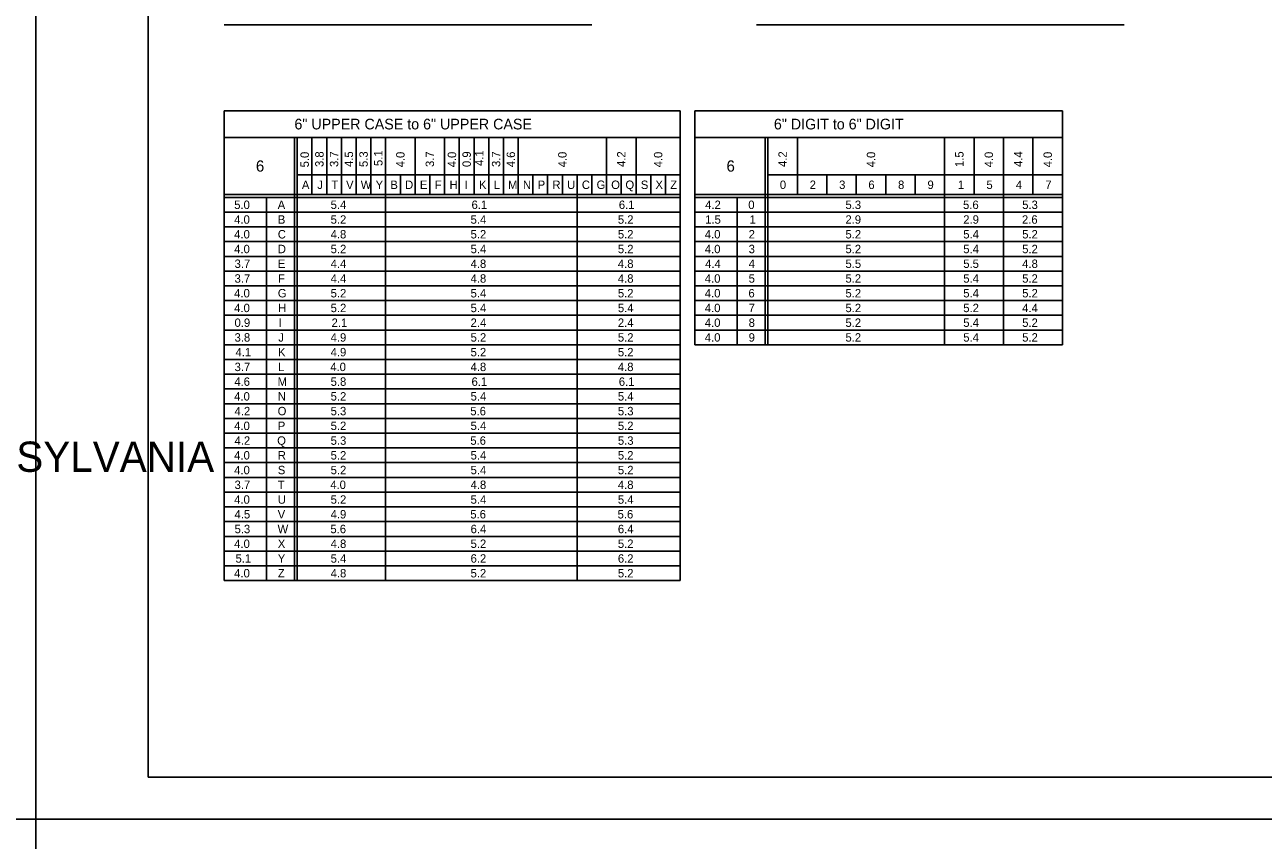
# Model space of a CAD drawing. Extents: x 637580 to 641849, y 297270 to 299646.
# Drawn here: x 640099.4 to 640540.8, y 297856.1 to 298146.6 of the extents above; entities that cross this region are included whole.
import ezdxf

# ---------------------------------------------------------------- set-up
doc = ezdxf.new("R2010")
doc.units = 0
for name, color, linetype in [('1', 7, 'Continuous'), ('2', 7, 'Continuous'), ('XCS-GRID-HVGL', 7, 'Continuous')]:
    doc.layers.add(name, color=color, linetype=linetype)

msp = doc.modelspace()

# ---------------------------------------------------------------- linework, layer by layer
at = {"layer": '1'}
for p, q in [((640143.31, 298442.63), (640143.31, 297878.63)), ((640929.31, 297878.63), (640143.31, 297878.63)), ((640143.31, 297878.63), (640729.31, 297878.63))]:
    msp.add_line(p, q, dxfattribs=at)
at = {"layer": '2'}
for p, q in [((640170.51, 298146.63), (640301.51, 298146.63)), ((640360.21, 298146.63), (640491.21, 298146.63)), ((640333.01, 298116), (640170.51, 298116)), ((640170.51, 298116), (640170.51, 297948.63)), ((640333.01, 298116), (640333.01, 297948.63)), ((640469.26, 298116), (640338.26, 298116)), ((640338.26, 298116), (640338.26, 298032.63)), ((640469.26, 298032.63), (640469.26, 298116)), ((640170.51, 298106.5), (640333.01, 298106.5)), ((640195.51, 298106.5), (640195.51, 297948.63)), ((640196.51, 298106.5), (640196.51, 297948.63)), ((640201.76, 298106.5), (640201.76, 298086.13)), ((640207.01, 298106.5), (640207.01, 298086.13)), ((640212.26, 298106.5), (640212.26, 298086.13)), ((640217.51, 298106.5), (640217.51, 298086.13)), ((640222.76, 298106.5), (640222.76, 298086.13)), ((640228.01, 298106.5), (640228.01, 297948.63)), ((640238.51, 298106.5), (640238.51, 298086.13)), ((640249.01, 298106.5), (640249.01, 298086.13)), ((640254.26, 298106.5), (640254.26, 298086.13)), ((640259.51, 298106.5), (640259.51, 298086.13)), ((640264.76, 298106.5), (640264.76, 298086.13)), ((640270.01, 298106.5), (640270.01, 298086.13)), ((640275.26, 298106.5), (640275.26, 298086.13)), ((640306.76, 298106.5), (640306.76, 298086.13)), ((640317.26, 298106.5), (640317.26, 298086.13)), ((640338.26, 298106.5), (640469.26, 298106.5)), ((640363.26, 298106.5), (640363.26, 298032.63)), ((640364.26, 298106.5), (640364.26, 298032.63)), ((640374.76, 298106.5), (640374.76, 298086.13)), ((640427.26, 298106.5), (640427.26, 298032.63)), ((640437.76, 298106.5), (640437.76, 298086.13)), ((640448.26, 298106.5), (640448.26, 298032.63)), ((640458.76, 298106.5), (640458.76, 298086.13)), ((640196.51, 298093.13), (640333.01, 298093.13)), ((640233.26, 298093.13), (640233.26, 298086.13)), ((640243.76, 298093.13), (640243.76, 298086.13)), ((640280.51, 298093.13), (640280.51, 298086.13)), ((640285.76, 298093.13), (640285.76, 298086.13)), ((640291.01, 298093.13), (640291.01, 298086.13)), ((640291.01, 298093.13), (640291.01, 298086.13)), ((640296.26, 298093.13), (640296.26, 297948.63)), ((640301.51, 298093.13), (640301.51, 298086.13)), ((640312.01, 298093.13), (640312.01, 298086.13)), ((640322.51, 298093.13), (640322.51, 298086.13)), ((640327.76, 298093.13), (640327.76, 298086.13)), ((640364.26, 298093.13), (640469.26, 298093.13)), ((640385.26, 298093.13), (640385.26, 298086.13)), ((640395.76, 298093.13), (640395.76, 298086.13)), ((640406.26, 298093.13), (640406.26, 298086.13)), ((640416.76, 298093.13), (640416.76, 298086.13)), ((640333.01, 298086.13), (640170.51, 298086.13)), ((640469.26, 298086.13), (640338.26, 298086.13)), ((640333.01, 298085.13), (640170.51, 298085.13)), ((640185.51, 298085.13), (640185.51, 297948.63)), ((640469.26, 298085.13), (640338.26, 298085.13)), ((640353.26, 298085.13), (640353.26, 298032.63)), ((640333.01, 298079.88), (640170.51, 298079.88)), ((640469.26, 298079.88), (640338.26, 298079.88)), ((640333.01, 298074.63), (640170.51, 298074.63)), ((640469.26, 298074.63), (640338.26, 298074.63)), ((640333.01, 298069.38), (640170.51, 298069.38)), ((640469.26, 298069.38), (640338.26, 298069.38)), ((640333.01, 298064.13), (640170.51, 298064.13)), ((640469.26, 298064.13), (640338.26, 298064.13)), ((640333.01, 298058.88), (640170.51, 298058.88)), ((640469.26, 298058.88), (640338.26, 298058.88)), ((640333.01, 298053.63), (640170.51, 298053.63)), ((640469.26, 298053.63), (640338.26, 298053.63)), ((640333.01, 298048.38), (640170.51, 298048.38)), ((640469.26, 298048.38), (640338.26, 298048.38)), ((640333.01, 298043.13), (640170.51, 298043.13)), ((640469.26, 298043.13), (640338.26, 298043.13)), ((640333.01, 298037.88), (640170.51, 298037.88)), ((640469.26, 298037.88), (640338.26, 298037.88)), ((640333.01, 298032.63), (640170.51, 298032.63)), ((640338.26, 298032.63), (640469.26, 298032.63)), ((640333.01, 298027.38), (640170.51, 298027.38)), ((640333.01, 298022.13), (640170.51, 298022.13)), ((640333.01, 298016.88), (640170.51, 298016.88)), ((640333.01, 298011.63), (640170.51, 298011.63)), ((640333.01, 298006.38), (640170.51, 298006.38)), ((640333.01, 298001.13), (640170.51, 298001.13)), ((640333.01, 297995.88), (640170.51, 297995.88)), ((640333.01, 297990.63), (640170.51, 297990.63)), ((640333.01, 297985.38), (640170.51, 297985.38)), ((640333.01, 297980.13), (640170.51, 297980.13)), ((640333.01, 297974.88), (640170.51, 297974.88)), ((640333.01, 297969.63), (640170.51, 297969.63)), ((640333.01, 297964.38), (640170.51, 297964.38)), ((640333.01, 297959.13), (640170.51, 297959.13)), ((640333.01, 297953.88), (640170.51, 297953.88)), ((640170.51, 297948.63), (640170.51, 297948.63)), ((640170.51, 297948.63), (640333.01, 297948.63))]:
    msp.add_line(p, q, dxfattribs=at)
at = {"layer": 'XCS-GRID-HVGL'}
for points in [[(639262.31, 298457.63), (640103.31, 298457.63), (640103.31, 297863.63), (639262.31, 297863.63)], [(640103.31, 298457.63), (640944.31, 298457.63), (640944.31, 297863.63), (640103.31, 297863.63)], [(639262.31, 297863.63), (640103.31, 297863.63), (640103.31, 297269.63), (639262.31, 297269.63)], [(640103.31, 297863.63), (640944.31, 297863.63), (640944.31, 297269.63), (640103.31, 297269.63)]]:
    msp.add_lwpolyline(points, close=True, dxfattribs=at)

# ---------------------------------------------------------------- texts
at = {"layer": '1'}
msp.add_text('COMMONWEALTH OF PENNSYLVANIA', height=10.7828, dxfattribs=at).set_placement((639900.9, 297987.36))
at = {"layer": '2'}
for s, height, p in [('6" UPPER CASE to 6" UPPER CASE', 3.8, (640195.5, 298109.35)), ('6" DIGIT to 6" DIGIT', 3.8, (640366.41, 298109.35)), ('6', 4, (640181.77, 298094.31)), ('6', 4, (640349.52, 298094.31)), ('A', 3, (640198.16, 298088.13)), ('J', 3, (640203.64, 298088.13)), ('T', 3, (640208.64, 298088.13)), ('V', 3, (640213.91, 298088.13)), ('W', 3, (640219.13, 298088.13)), ('Y', 3, (640224.44, 298088.13)), ('B', 3, (640229.7, 298088.13)), ('D', 3, (640234.95, 298088.13)), ('E', 3, (640240.22, 298088.13)), ('F', 3, (640245.52, 298088.13)), ('H', 3, (640250.79, 298088.13)), ('I', 3, (640256.2, 298088.13)), ('K', 3, (640261.29, 298088.13)), ('L', 3, (640266.54, 298088.13)), ('M', 3, (640271.63, 298088.13)), ('N', 3, (640276.95, 298088.13)), ('P', 3, (640282.2, 298088.13)), ('R', 3, (640287.45, 298088.13)), ('U', 3, (640292.69, 298088.13)), ('C', 3, (640297.95, 298088.13)), ('G', 3, (640303.2, 298088.13)), ('O', 3, (640308.41, 298088.13)), ('Q', 3, (640313.48, 298088.13)), ('S', 3, (640318.97, 298088.13)), ('X', 3, (640324.19, 298088.13)), ('Z', 3, (640329.45, 298088.13)), ('0', 3, (640368.53, 298088.13)), ('2', 3, (640379.16, 298088.13)), ('3', 3, (640389.66, 298088.13)), ('6', 3, (640400.08, 298088.13)), ('8', 3, (640410.66, 298088.13)), ('9', 3, (640421.15, 298088.13)), ('1', 3, (640432, 298088.13)), ('5', 3, (640442.16, 298088.13)), ('4', 3, (640452.66, 298088.13)), ('7', 3, (640463.16, 298088.13)), ('5.0', 3, (640174.03, 298081)), ('A', 3, (640189.53, 298081)), ('5.4', 3, (640208.41, 298081)), ('6.1', 3, (640258.63, 298081)), ('6.1', 3, (640311.13, 298081)), ('4.2', 3, (640341.91, 298081)), ('0', 3, (640357.28, 298081)), ('5.3', 3, (640391.91, 298081)), ('5.6', 3, (640433.83, 298081)), ('5.3', 3, (640454.91, 298081)), ('4.0', 3, (640174.03, 298075.75)), ('B', 3, (640189.58, 298075.75)), ('5.2', 3, (640208.41, 298075.75)), ('5.4', 3, (640258.29, 298075.75)), ('5.2', 3, (640310.79, 298075.75)), ('1.5', 3, (640341.91, 298075.75)), ('1', 3, (640357.75, 298075.75)), ('2.9', 3, (640391.9, 298075.75)), ('2.9', 3, (640433.9, 298075.75)), ('2.6', 3, (640454.83, 298075.75)), ('4.0', 3, (640174.03, 298070.5)), ('C', 3, (640189.58, 298070.5)), ('4.8', 3, (640208.41, 298070.5)), ('5.2', 3, (640258.29, 298070.5)), ('5.2', 3, (640310.79, 298070.5)), ('4.0', 3, (640341.78, 298070.5)), ('2', 3, (640357.41, 298070.5)), ('5.2', 3, (640391.91, 298070.5)), ('5.4', 3, (640433.91, 298070.5)), ('5.2', 3, (640454.91, 298070.5)), ('4.0', 3, (640174.03, 298065.25)), ('D', 3, (640189.58, 298065.25)), ('5.2', 3, (640208.41, 298065.25)), ('5.4', 3, (640258.29, 298065.25)), ('5.2', 3, (640310.79, 298065.25)), ('4.0', 3, (640341.78, 298065.25)), ('3', 3, (640357.41, 298065.25)), ('5.2', 3, (640391.91, 298065.25)), ('5.4', 3, (640433.91, 298065.25)), ('5.2', 3, (640454.91, 298065.25)), ('3.7', 3, (640174.16, 298060)), ('E', 3, (640189.59, 298060)), ('4.4', 3, (640208.41, 298060)), ('4.8', 3, (640258.29, 298060)), ('4.8', 3, (640310.79, 298060)), ('4.4', 3, (640341.91, 298060)), ('4', 3, (640357.41, 298060)), ('5.5', 3, (640391.91, 298060)), ('5.5', 3, (640433.91, 298060)), ('4.8', 3, (640454.91, 298060)), ('3.7', 3, (640174.16, 298054.75)), ('F', 3, (640189.65, 298054.75)), ('4.4', 3, (640208.41, 298054.75)), ('4.8', 3, (640258.29, 298054.75)), ('4.8', 3, (640310.79, 298054.75)), ('4.0', 3, (640341.78, 298054.75)), ('5', 3, (640357.41, 298054.75)), ('5.2', 3, (640391.91, 298054.75)), ('5.4', 3, (640433.91, 298054.75)), ('5.2', 3, (640454.91, 298054.75)), ('4.0', 3, (640174.03, 298049.5)), ('G', 3, (640189.58, 298049.5)), ('5.2', 3, (640208.41, 298049.5)), ('5.4', 3, (640258.29, 298049.5)), ('5.2', 3, (640310.79, 298049.5)), ('4.0', 3, (640341.78, 298049.5)), ('6', 3, (640357.33, 298049.5)), ('5.2', 3, (640391.91, 298049.5)), ('5.4', 3, (640433.91, 298049.5)), ('5.2', 3, (640454.91, 298049.5)), ('4.0', 3, (640174.03, 298044.25)), ('H', 3, (640189.66, 298044.25)), ('5.2', 3, (640208.41, 298044.25)), ('5.4', 3, (640258.29, 298044.25)), ('5.4', 3, (640310.79, 298044.25)), ('4.0', 3, (640341.78, 298044.25)), ('7', 3, (640357.41, 298044.25)), ('5.2', 3, (640391.91, 298044.25)), ('5.2', 3, (640433.91, 298044.25)), ('4.4', 3, (640454.91, 298044.25)), ('0.9', 3, (640174.15, 298039)), ('I', 3, (640189.83, 298039)), ('2.1', 3, (640208.75, 298039)), ('2.4', 3, (640258.29, 298039)), ('2.4', 3, (640310.79, 298039)), ('4.0', 3, (640341.78, 298039)), ('8', 3, (640357.41, 298039)), ('5.2', 3, (640391.91, 298039)), ('5.4', 3, (640433.91, 298039)), ('5.2', 3, (640454.91, 298039)), ('3.8', 3, (640174.16, 298033.75)), ('J', 3, (640189.77, 298033.75)), ('4.9', 3, (640208.4, 298033.75)), ('5.2', 3, (640258.29, 298033.75)), ('5.2', 3, (640310.79, 298033.75)), ('4.0', 3, (640341.78, 298033.75)), ('9', 3, (640357.4, 298033.75)), ('5.2', 3, (640391.91, 298033.75)), ('5.4', 3, (640433.91, 298033.75)), ('5.2', 3, (640454.91, 298033.75)), ('4.1', 3, (640174.5, 298028.5)), ('K', 3, (640189.66, 298028.5)), ('4.9', 3, (640208.4, 298028.5)), ('5.2', 3, (640258.29, 298028.5)), ('5.2', 3, (640310.79, 298028.5)), ('3.7', 3, (640174.16, 298023.25)), ('L', 3, (640189.66, 298023.25)), ('4.0', 3, (640208.28, 298023.25)), ('4.8', 3, (640258.29, 298023.25)), ('4.8', 3, (640310.79, 298023.25)), ('4.6', 3, (640174.08, 298018)), ('M', 3, (640189.51, 298018)), ('5.8', 3, (640208.41, 298018)), ('6.1', 3, (640258.63, 298018)), ('6.1', 3, (640311.13, 298018)), ('4.0', 3, (640174.03, 298012.75)), ('N', 3, (640189.58, 298012.75)), ('5.2', 3, (640208.41, 298012.75)), ('5.4', 3, (640258.29, 298012.75)), ('5.4', 3, (640310.79, 298012.75)), ('4.2', 3, (640174.16, 298007.5)), ('O', 3, (640189.53, 298007.5)), ('5.3', 3, (640208.41, 298007.5)), ('5.6', 3, (640258.2, 298007.5)), ('5.3', 3, (640310.79, 298007.5)), ('4.0', 3, (640174.03, 298002.25)), ('P', 3, (640189.58, 298002.25)), ('5.2', 3, (640208.41, 298002.25)), ('5.4', 3, (640258.29, 298002.25)), ('5.2', 3, (640310.79, 298002.25)), ('4.2', 3, (640174.16, 297997)), ('Q', 3, (640189.35, 297997)), ('5.3', 3, (640208.41, 297997)), ('5.6', 3, (640258.2, 297997)), ('5.3', 3, (640310.79, 297997)), ('4.0', 3, (640174.03, 297991.75)), ('R', 3, (640189.58, 297991.75)), ('5.2', 3, (640208.41, 297991.75)), ('5.4', 3, (640258.29, 297991.75)), ('5.2', 3, (640310.79, 297991.75)), ('4.0', 3, (640174.03, 297986.5)), ('S', 3, (640189.59, 297986.5)), ('5.2', 3, (640208.41, 297986.5)), ('5.4', 3, (640258.29, 297986.5)), ('5.2', 3, (640310.79, 297986.5)), ('3.7', 3, (640174.16, 297981.25)), ('4.0', 3, (640208.28, 297981.25)), ('4.8', 3, (640258.29, 297981.25)), ('4.8', 3, (640310.79, 297981.25)), ('T', 3, (640189.52, 297981.25)), ('4.0', 3, (640174.03, 297976)), ('U', 3, (640189.57, 297976)), ('5.2', 3, (640208.41, 297976)), ('5.4', 3, (640258.29, 297976)), ('5.4', 3, (640310.79, 297976)), ('4.5', 3, (640174.16, 297970.75)), ('V', 3, (640189.53, 297970.75)), ('4.9', 3, (640208.4, 297970.75)), ('5.6', 3, (640258.2, 297970.75)), ('5.6', 3, (640310.7, 297970.75)), ('5.3', 3, (640174.16, 297965.5)), ('W', 3, (640189.51, 297965.5)), ('5.6', 3, (640208.33, 297965.5)), ('6.4', 3, (640258.29, 297965.5)), ('6.4', 3, (640310.79, 297965.5)), ('4.0', 3, (640174.03, 297960.25)), ('X', 3, (640189.57, 297960.25)), ('4.8', 3, (640208.41, 297960.25)), ('5.2', 3, (640258.29, 297960.25)), ('5.2', 3, (640310.79, 297960.25)), ('5.1', 3, (640174.5, 297955)), ('Y', 3, (640189.57, 297955)), ('5.4', 3, (640208.41, 297955)), ('6.2', 3, (640258.29, 297955)), ('6.2', 3, (640310.79, 297955)), ('4.0', 3, (640174.03, 297949.75)), ('Z', 3, (640189.58, 297949.75)), ('4.8', 3, (640208.41, 297949.75)), ('5.2', 3, (640258.29, 297949.75)), ('5.2', 3, (640310.79, 297949.75))]:
    msp.add_text(s, height=height, dxfattribs=at).set_placement(p)
for s, p in [('5.0', (640200.64, 298095.83)), ('3.8', (640205.89, 298095.96)), ('3.7', (640211.14, 298095.96)), ('4.5', (640216.39, 298095.96)), ('5.3', (640221.64, 298095.96)), ('5.1', (640226.89, 298096.31)), ('4.0', (640234.76, 298095.83)), ('3.7', (640245.26, 298095.96)), ('4.0', (640253.14, 298095.83)), ('0.9', (640258.39, 298095.95)), ('4.1', (640262.87, 298096.31)), ('3.7', (640268.89, 298095.96)), ('4.6', (640274.14, 298095.88)), ('4.0', (640292.51, 298095.83)), ('4.2', (640313.51, 298095.96)), ('4.0', (640326.64, 298095.83)), ('4.2', (640371.01, 298095.96)), ('4.0', (640402.51, 298095.83)), ('1.5', (640434.01, 298095.96)), ('4.0', (640444.51, 298095.83)), ('4.4', (640455.01, 298095.96)), ('4.0', (640465.51, 298095.83))]:
    msp.add_text(s, height=3, rotation=90, dxfattribs=at).set_placement(p)

doc.saveas('drawing.dxf')
